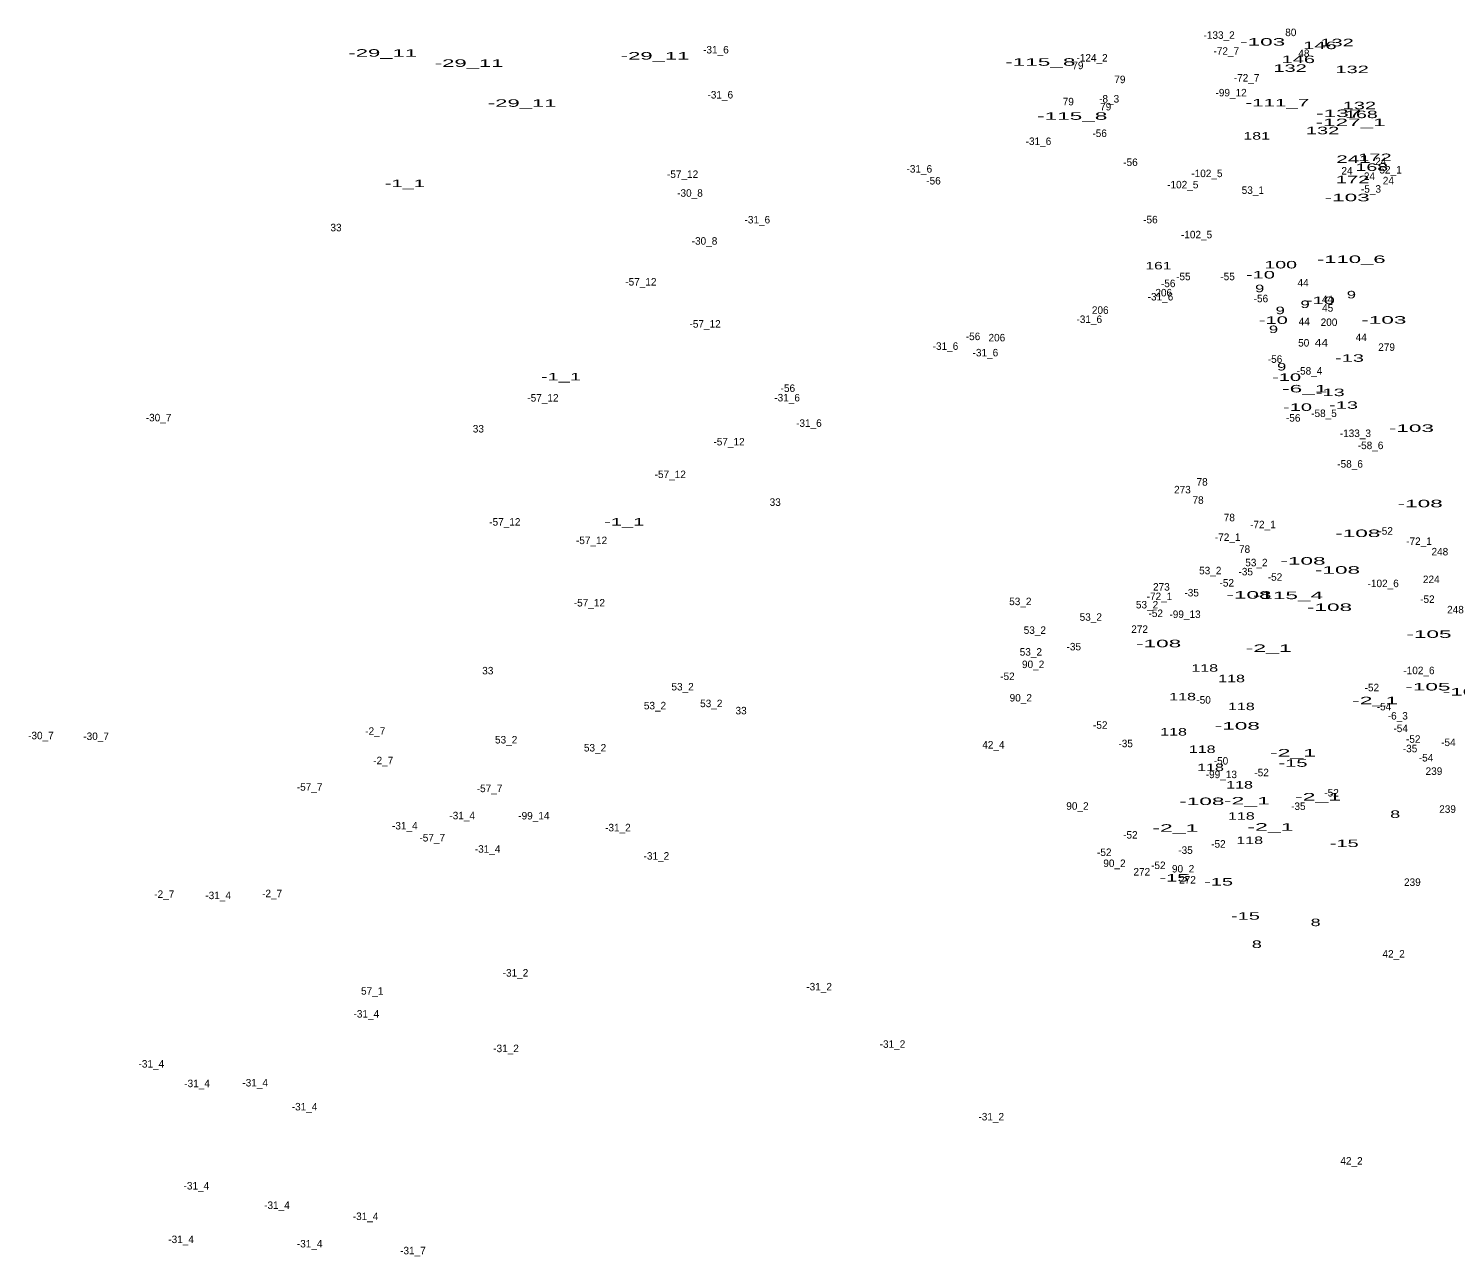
# Model space of a CAD drawing. Extents: x -656096 to -652763, y -1002270 to -998958.
# Drawn here: x -656096 to -655334, y -1000705 to -1000050 of the extents above; entities that cross this region are included whole.
import ezdxf
from ezdxf.enums import TextEntityAlignment as Align

# ---------------------------------------------------------------- set-up
doc = ezdxf.new("R2010")
doc.units = 0
doc.header["$LTSCALE"] = 1.6
doc.layers.add('24', color=7, linetype='Continuous')

msp = doc.modelspace()

# ---------------------------------------------------------------- texts
at = {"layer": '24'}
for s, p in [('-133_2', (-655460.256, -1000055.13)), ('80', (-655421.991, -1000053.69)), ('-31_6', (-655728.872, -1000062.94)), ('-72_7', (-655456.424, -1000063.63)), ('48', (-655415.001, -1000064.84)), ('79', (-655535.638, -1000071.33)), ('-124_2', (-655528.09, -1000067.27)), ('79', (-655513.238, -1000078.8)), ('-72_7', (-655445.584, -1000077.94)), ('-31_6', (-655726.542, -1000086.99)), ('-99_12', (-655453.867, -1000085.86)), ('79', (-655540.768, -1000090.63)), ('-8_3', (-655518.963, -1000089.16)), ('79', (-655520.808, -1000093.35)), ('-56', (-655524.04, -1000107.53)), ('-31_6', (-655556.712, -1000111.81)), ('-56', (-655507.58, -1000123.02)), ('24', (-655373.971, -1000122.53)), ('-57_12', (-655746.662, -1000129.41)), ('-31_6', (-655620.302, -1000126.55)), ('-56', (-655612.72, -1000132.9)), ('-102_5', (-655466.77, -1000128.98)), ('24', (-655392.001, -1000127.58)), ('24', (-655380.001, -1000130.48)), ('52_1', (-655368.739, -1000127.04)), ('24', (-655369.901, -1000132.81)), ('-30_8', (-655742.726, -1000139.45)), ('-102_5', (-655479.66, -1000134.97)), ('53_1', (-655442.259, -1000137.92)), ('-5_3', (-655379.193, -1000137.27)), ('-31_6', (-655706.772, -1000153.7)), ('-56', (-655496.93, -1000153.63)), ('33', (-655931.677, -1000157.88)), ('-102_5', (-655472.3, -1000161.64)), ('-30_8', (-655734.976, -1000165.05)), ('-57_12', (-655768.922, -1000186.86)), ('-55', (-655479.365, -1000184.01)), ('-55', (-655455.745, -1000184.01)), ('44', (-655415.406, -1000187.32)), ('-31_6', (-655491.572, -1000194.82)), ('206', (-655489.837, -1000192.66)), ('-56', (-655487.44, -1000187.72)), ('206', (-655523.727, -1000201.96)), ('-56', (-655437.95, -1000195.78)), ('44', (-655402.416, -1000196.24)), ('45', (-655402.321, -1000200.8)), ('-57_12', (-655734.652, -1000209.33)), ('-31_6', (-655529.572, -1000206.84)), ('44', (-655414.826, -1000208.07)), ('200', (-655401.595, -1000208.45)), ('-56', (-655591.62, -1000216)), ('206', (-655578.907, -1000216.68)), ('44', (-655384.386, -1000216.51)), ('-31_6', (-655606.342, -1000221.19)), ('-31_6', (-655585.022, -1000224.68)), ('50', (-655415.101, -1000219.45)), ('279', (-655370.858, -1000221.73)), ('-56', (-655430.4, -1000228.13)), ('-58_4', (-655411.997, -1000234.41)), ('-56', (-655690.48, -1000243.65)), ('-57_12', (-655821.212, -1000248.82)), ('-31_6', (-655690.872, -1000248.73)), ('-30_7', (-656026.392, -1000259.36)), ('-31_6', (-655679.242, -1000262.31)), ('-56', (-655420.72, -1000259.51)), ('-58_5', (-655404.282, -1000257.07)), ('33', (-655855.687, -1000265.32)), ('-133_3', (-655387.526, -1000267.74)), ('-57_12', (-655721.872, -1000272.23)), ('-58_6', (-655379.408, -1000274.21)), ('-58_6', (-655390.348, -1000284.09)), ('-57_12', (-655753.242, -1000289.66)), ('78', (-655469.353, -1000293.7)), ('273', (-655479.843, -1000297.83)), ('33', (-655697.217, -1000304.5)), ('78', (-655471.493, -1000303.4)), ('-57_12', (-655841.542, -1000315.06)), ('78', (-655454.813, -1000312.71)), ('-72_1', (-655436.902, -1000316.46)), ('-72_1', (-655455.692, -1000323.24)), ('-52', (-655371.365, -1000319.89)), ('-57_12', (-655795.262, -1000324.92)), ('78', (-655446.673, -1000329.58)), ('-72_1', (-655353.562, -1000325.37)), ('248', (-655342.421, -1000330.95)), ('53_2', (-655440.365, -1000336.76)), ('53_2', (-655464.985, -1000341.03)), ('-35', (-655446.055, -1000341.61)), ('-52', (-655430.425, -1000344.49)), ('224', (-655347.021, -1000345.73)), ('-72_1', (-655492.092, -1000354.81)), ('273', (-655491.073, -1000349.74)), ('-35', (-655474.915, -1000352.85)), ('-52', (-655456.175, -1000347.59)), ('-102_6', (-655372.676, -1000347.9)), ('-57_12', (-655796.422, -1000358.23)), ('53_2', (-655566.375, -1000357.51)), ('53_2', (-655498.725, -1000359.27)), ('-52', (-655349.095, -1000356.31)), ('248', (-655334.091, -1000361.9)), ('53_2', (-655528.765, -1000365.85)), ('-52', (-655494.095, -1000363.86)), ('-99_13', (-655478.457, -1000364.36)), ('53_2', (-655558.625, -1000372.84)), ('272', (-655502.693, -1000372.32)), ('53_2', (-655560.755, -1000384.47)), ('-35', (-655537.835, -1000381.66)), ('90_2', (-655559.544, -1000391.11)), ('33', (-655850.647, -1000394.48)), ('-52', (-655573.265, -1000397.5)), ('-102_6', (-655353.576, -1000394.37)), ('53_2', (-655746.675, -1000403.05)), ('-52', (-655378.725, -1000403.51)), ('53_2', (-655761.405, -1000413.14)), ('53_2', (-655731.355, -1000411.98)), ('33', (-655715.437, -1000415.82)), ('90_2', (-655566.144, -1000408.95)), ('-50', (-655468.549, -1000410.09)), ('-54', (-655372.259, -1000413.67)), ('-52', (-655523.715, -1000423.51)), ('-6_3', (-655364.879, -1000418.61)), ('-30_7', (-656089.212, -1000429.12)), ('-30_7', (-656059.742, -1000429.51)), ('-2_7', (-655910.729, -1000426.75)), ('-54', (-655363.349, -1000425.3)), ('-52', (-655356.645, -1000431.01)), ('53_2', (-655840.855, -1000431.37)), ('53_2', (-655793.395, -1000435.64)), ('42_4', (-655580.744, -1000434.06)), ('-35', (-655510.145, -1000433.37)), ('-35', (-655358.335, -1000436.06)), ('-54', (-655337.889, -1000432.75)), ('-2_7', (-655906.459, -1000442.46)), ('-50', (-655459.259, -1000442.63)), ('-54', (-655349.799, -1000440.99)), ('-99_13', (-655459.067, -1000449.88)), ('-52', (-655437.585, -1000448.87)), ('239', (-655345.573, -1000448.14)), ('-57_7', (-655945.764, -1000456.59)), ('-57_7', (-655849.714, -1000457.36)), ('-52', (-655400.215, -1000459.68)), ('90_2', (-655535.894, -1000466.75)), ('-35', (-655417.975, -1000466.86)), ('239', (-655338.313, -1000468.39)), ('-31_4', (-655864.32, -1000471.85)), ('-99_14', (-655826.061, -1000471.94)), ('-31_4', (-655894.95, -1000477.28)), ('-57_7', (-655880.314, -1000483.7)), ('-31_2', (-655781.206, -1000478.27)), ('-52', (-655507.645, -1000482.16)), ('-31_4', (-655850.75, -1000489.69)), ('-52', (-655521.565, -1000491.45)), ('-35', (-655478.195, -1000490.3)), ('-52', (-655460.635, -1000486.99)), ('-31_2', (-655760.656, -1000493.4)), ('90_2', (-655516.124, -1000497.33)), ('-52', (-655492.715, -1000498.42)), ('272', (-655501.533, -1000501.88)), ('90_2', (-655479.484, -1000500.24)), ('272', (-655477.133, -1000506.14)), ('-2_7', (-656023.359, -1000513.83)), ('-31_4', (-655994.6, -1000514.47)), ('-2_7', (-655965.779, -1000513.44)), ('239', (-655357.103, -1000507.42)), ('42_2', (-655367.1, -1000545.67)), ('-31_2', (-655835.876, -1000555.84)), ('57_1', (-655912.364, -1000565.49)), ('-31_2', (-655673.796, -1000563.21)), ('-31_4', (-655915.5, -1000577.74)), ('-31_2', (-655840.916, -1000596.18)), ('-31_2', (-655634.636, -1000593.86)), ('-31_4', (-656030.27, -1000604.44)), ('-31_4', (-656005.85, -1000614.88)), ('-31_4', (-655974.83, -1000614.5)), ('-31_4', (-655948.46, -1000627.3)), ('-31_2', (-655581.906, -1000632.64)), ('42_2', (-655389.59, -1000656.22)), ('-31_4', (-656006.23, -1000669.52)), ('-31_4', (-655963.2, -1000679.9)), ('-31_4', (-655915.89, -1000685.81)), ('-31_4', (-656014.38, -1000698.13)), ('-31_4', (-655945.75, -1000700.46)), ('-31_7', (-655890.612, -1000704.12))]:
    msp.add_text(s, height=4, dxfattribs=at).set_placement(p, align=Align.CENTER)
for s, width, p in [('-29_11', 2.2, (-655906.753, -1000064.66)), ('-103', 2.25, (-655437.007, -1000058.76)), ('146', 2, (-655406.458, -1000060.62)), ('132', 2, (-655397.307, -1000059.1)), ('-29_11', 2.2, (-655860.613, -1000070.09)), ('-29_11', 2.2, (-655761.353, -1000066.21)), ('-115_8', 2.25, (-655555.707, -1000069.5)), ('132', 2, (-655422.377, -1000072.76)), ('146', 2, (-655417.978, -1000068.08)), ('132', 2, (-655389.267, -1000073.44)), ('-29_11', 2.2, (-655832.313, -1000091.42)), ('-111_7', 2.05, (-655429.229, -1000091.23)), ('132', 2, (-655385.397, -1000092.72)), ('-115_8', 2.25, (-655538.667, -1000098.36)), ('-127_1', 2.25, (-655390.073, -1000101.74)), ('-137', 2.25, (-655396.425, -1000096.88)), ('168', 1.95, (-655384.283, -1000097.46)), ('181', 1.6, (-655440.214, -1000108.94)), ('132', 2, (-655405.047, -1000106.08)), ('241', 2.05, (-655388.543, -1000121.36)), ('168', 1.95, (-655378.753, -1000125.65)), ('172', 2, (-655377.103, -1000120.4)), ('172', 2, (-655389.003, -1000132.23)), ('-1_1', 2, (-655894.927, -1000134.3)), ('-103', 2.25, (-655391.917, -1000141.85)), ('161', 1.55, (-655492.669, -1000178.24)), ('100', 1.95, (-655427.39, -1000177.72)), ('-110_6', 2.2, (-655389.719, -1000174.81)), ('-10', 2, (-655438.197, -1000183.08)), ('9', 1.65, (-655438.606, -1000190.41)), ('9', 1.65, (-655389.656, -1000193.7)), ('9', 1.65, (-655427.646, -1000202.14)), ('9', 1.65, (-655414.366, -1000198.84)), ('-10', 2, (-655406.207, -1000196.76)), ('-10', 2, (-655431.317, -1000207.33)), ('-103', 2.25, (-655372.337, -1000207.21)), ('9', 1.65, (-655431.236, -1000212.22)), ('44', 1.2, (-655405.67, -1000219.41)), ('9', 1.65, (-655426.876, -1000232.2)), ('-13', 2, (-655390.671, -1000227.57)), ('-1_1', 2, (-655811.567, -1000237.48)), ('-10', 2, (-655424.237, -1000237.78)), ('-6_1', 2.25, (-655414.567, -1000243.92)), ('-13', 2, (-655400.941, -1000245.9)), ('-10', 2, (-655418.417, -1000253.78)), ('-13', 2, (-655393.861, -1000252.68)), ('-103', 2.25, (-655357.607, -1000265.02)), ('-108', 2.25, (-655352.937, -1000305.26)), ('-1_1', 2, (-655777.827, -1000315.05)), ('-108', 2.25, (-655386.237, -1000321.14)), ('-108', 2.25, (-655415.477, -1000335.87)), ('-108', 2.25, (-655397.077, -1000340.71)), ('-108', 2.25, (-655444.327, -1000354.03)), ('-115_4', 2.25, (-655423.523, -1000354.29)), ('-108', 2.25, (-655401.337, -1000360.62)), ('-105', 2.25, (-655348.237, -1000374.99)), ('-108', 2.25, (-655492.547, -1000379.99)), ('-2_1', 2.3, (-655433.811, -1000382.5)), ('118', 1.6, (-655467.934, -1000393.05)), ('118', 1.6, (-655453.604, -1000398.67)), ('-105', 2.25, (-655348.817, -1000403.08)), ('-105', 2.25, (-655328.867, -1000405.79)), ('118', 1.6, (-655479.744, -1000408.35)), ('118', 1.6, (-655448.374, -1000413.58)), ('-2_1', 2.3, (-655377.001, -1000410.43)), ('118', 1.6, (-655484.584, -1000427.14)), ('-108', 2.25, (-655450.527, -1000423.96)), ('118', 1.6, (-655469.294, -1000436.44)), ('-2_1', 2.3, (-655420.821, -1000438.35)), ('118', 1.6, (-655464.834, -1000446.12)), ('-15', 2, (-655420.801, -1000443.81)), ('118', 1.6, (-655449.344, -1000455.42)), ('-108', 2.25, (-655469.497, -1000464.25)), ('-2_1', 2.3, (-655445.441, -1000463.95)), ('-2_1', 2.3, (-655407.441, -1000461.82)), ('118', 1.6, (-655448.374, -1000472.07)), ('8', 1.8, (-655366.281, -1000471.11)), ('-2_1', 2.3, (-655483.631, -1000478.5)), ('-2_1', 2.3, (-655432.841, -1000477.92)), ('118', 1.6, (-655443.924, -1000485.05)), ('-15', 2, (-655393.471, -1000486.67)), ('-15', 2, (-655484.391, -1000505.1)), ('-15', 2, (-655460.551, -1000507.23)), ('-15', 2, (-655446.201, -1000525.46)), ('8', 1.8, (-655408.741, -1000528.9)), ('8', 1.8, (-655440.141, -1000540.54))]:
    msp.add_text(s, height=4, dxfattribs=dict(at, width=width)).set_placement(p, align=Align.CENTER)

doc.saveas('drawing.dxf')
